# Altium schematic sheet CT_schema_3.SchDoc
size 293 x 134 mm
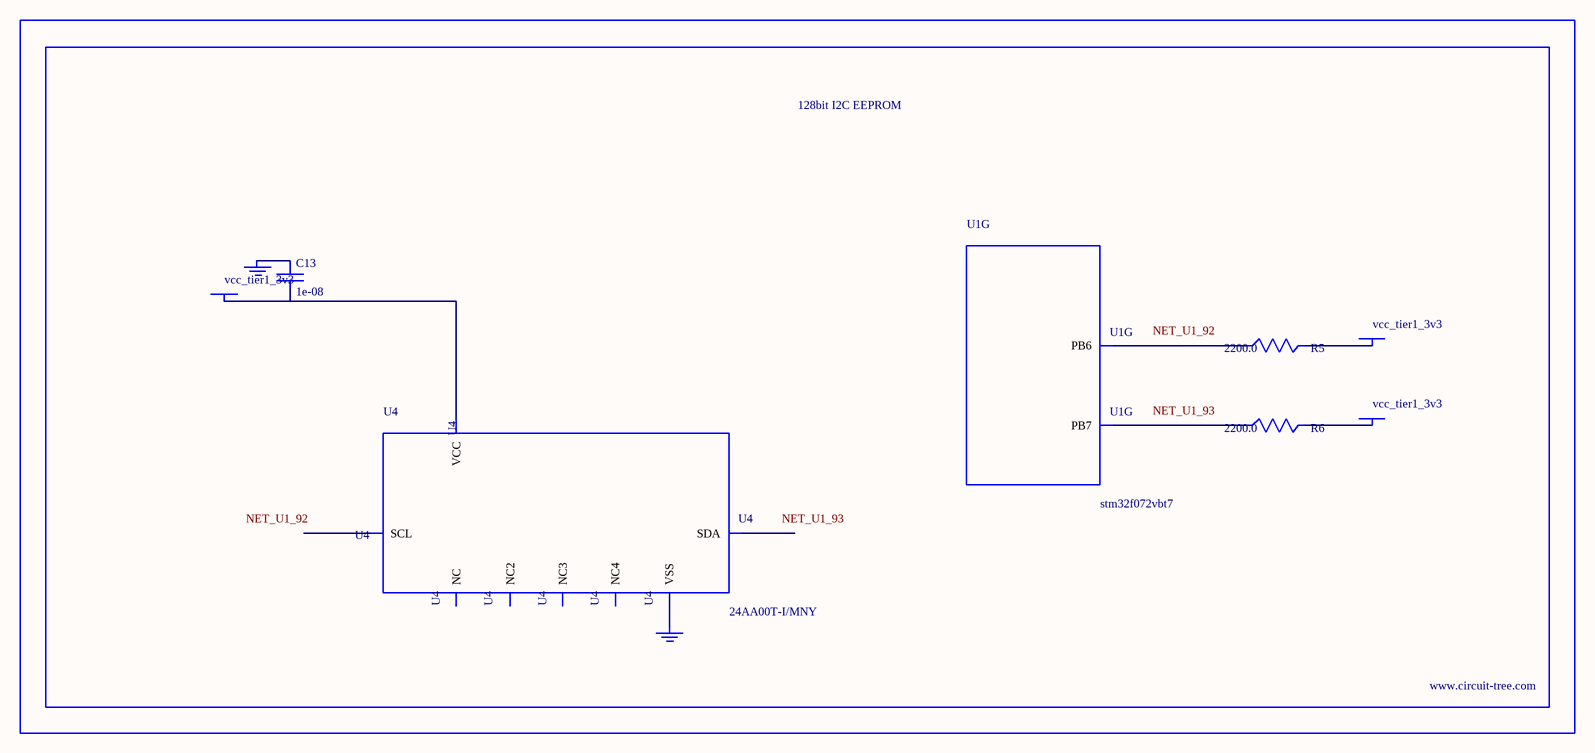
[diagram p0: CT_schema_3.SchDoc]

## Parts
BORDER2  (no value)
C13  1e-08  [C0402]
GND_INSTANCE_2_0  (no value)
GND_INSTANCE_2_1  (no value)
POWER_INSTANCE_2_0  vcc_tier1_3v3
POWER_INSTANCE_2_1  vcc_tier1_3v3
POWER_INSTANCE_2_2  vcc_tier1_3v3
R5  2200.0  [R0603]
R6  2200.0  [R0603]
U1  stm32f072vbt7  [LQFP100]  (part G of 10)
U4  24AA00T-I/MNY  [TDFN-8/6MM]

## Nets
NetC13_1: C13.1 GND_INSTANCE_2_0.0(GND)
NetC13_2: C13.2 POWER_INSTANCE_2_0.0(PWR) U4.8(VCC)
NetGND_INSTANCE_2_1_0: GND_INSTANCE_2_1.0(GND) U4.4(VSS)
NetPOWER_INSTANCE_2_1_0: POWER_INSTANCE_2_1.0(PWR) R5.2
NetPOWER_INSTANCE_2_2_0: POWER_INSTANCE_2_2.0(PWR) R6.2
NetR5_1: R5.1 U1.92(PB6)
NetR6_1: R6.1 U1.93(PB7)

Not connected (* = marked no-connect by the designer): U4 1(NC) 2(NC2) 3(NC3) 5(SDA) 6(SCL) 7(NC4)

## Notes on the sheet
- Labels drawn without touching a wire or pin: NET_U1_92, NET_U1_93

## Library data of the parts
BORDER2 = BORDER_PAGE2
C13 = C0402C103K3RAC
GND_INSTANCE_2_0 GND_INSTANCE_2_1 = GND
POWER_INSTANCE_2_0-POWER_INSTANCE_2_2 = PWR
R5 R6 = RC0603JR-072K2L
